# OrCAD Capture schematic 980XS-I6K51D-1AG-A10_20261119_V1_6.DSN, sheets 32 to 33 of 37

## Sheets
32 P0022_S2_USB/AUD/FLASH/XTAL: size A1
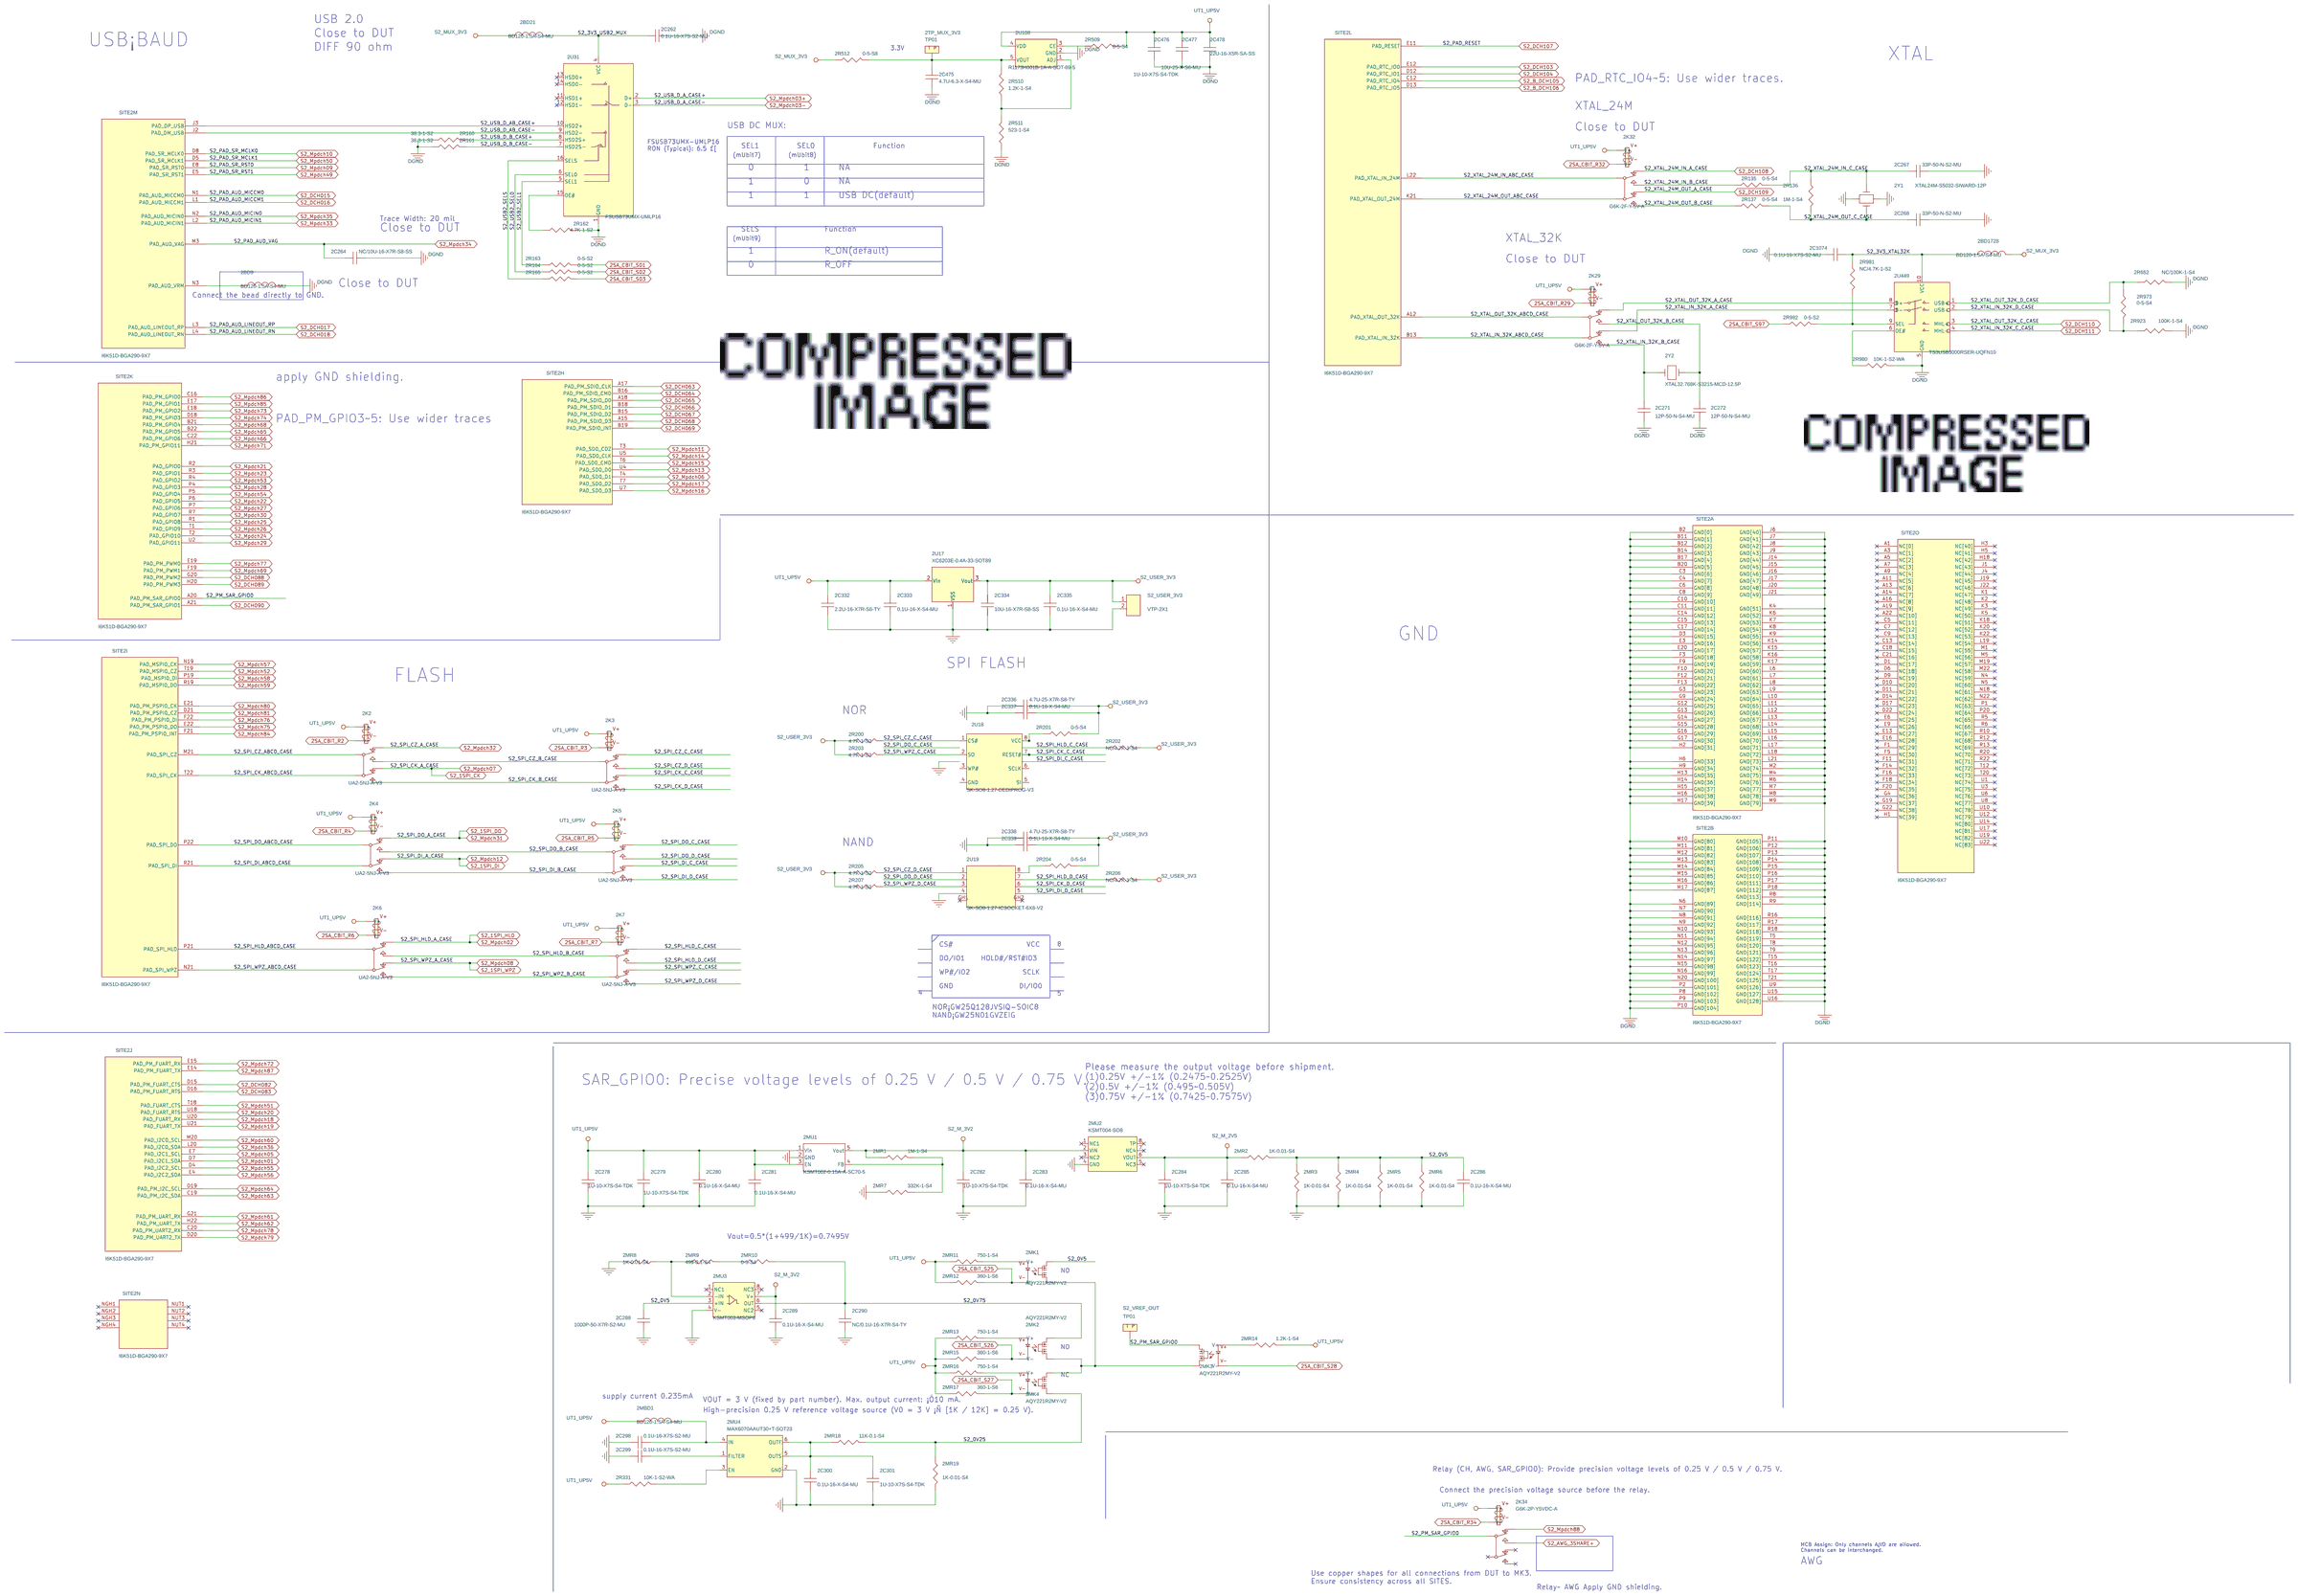
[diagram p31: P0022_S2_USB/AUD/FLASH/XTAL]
33 P0052_S5_USB/AUD/FLASH/XTAL: size A1
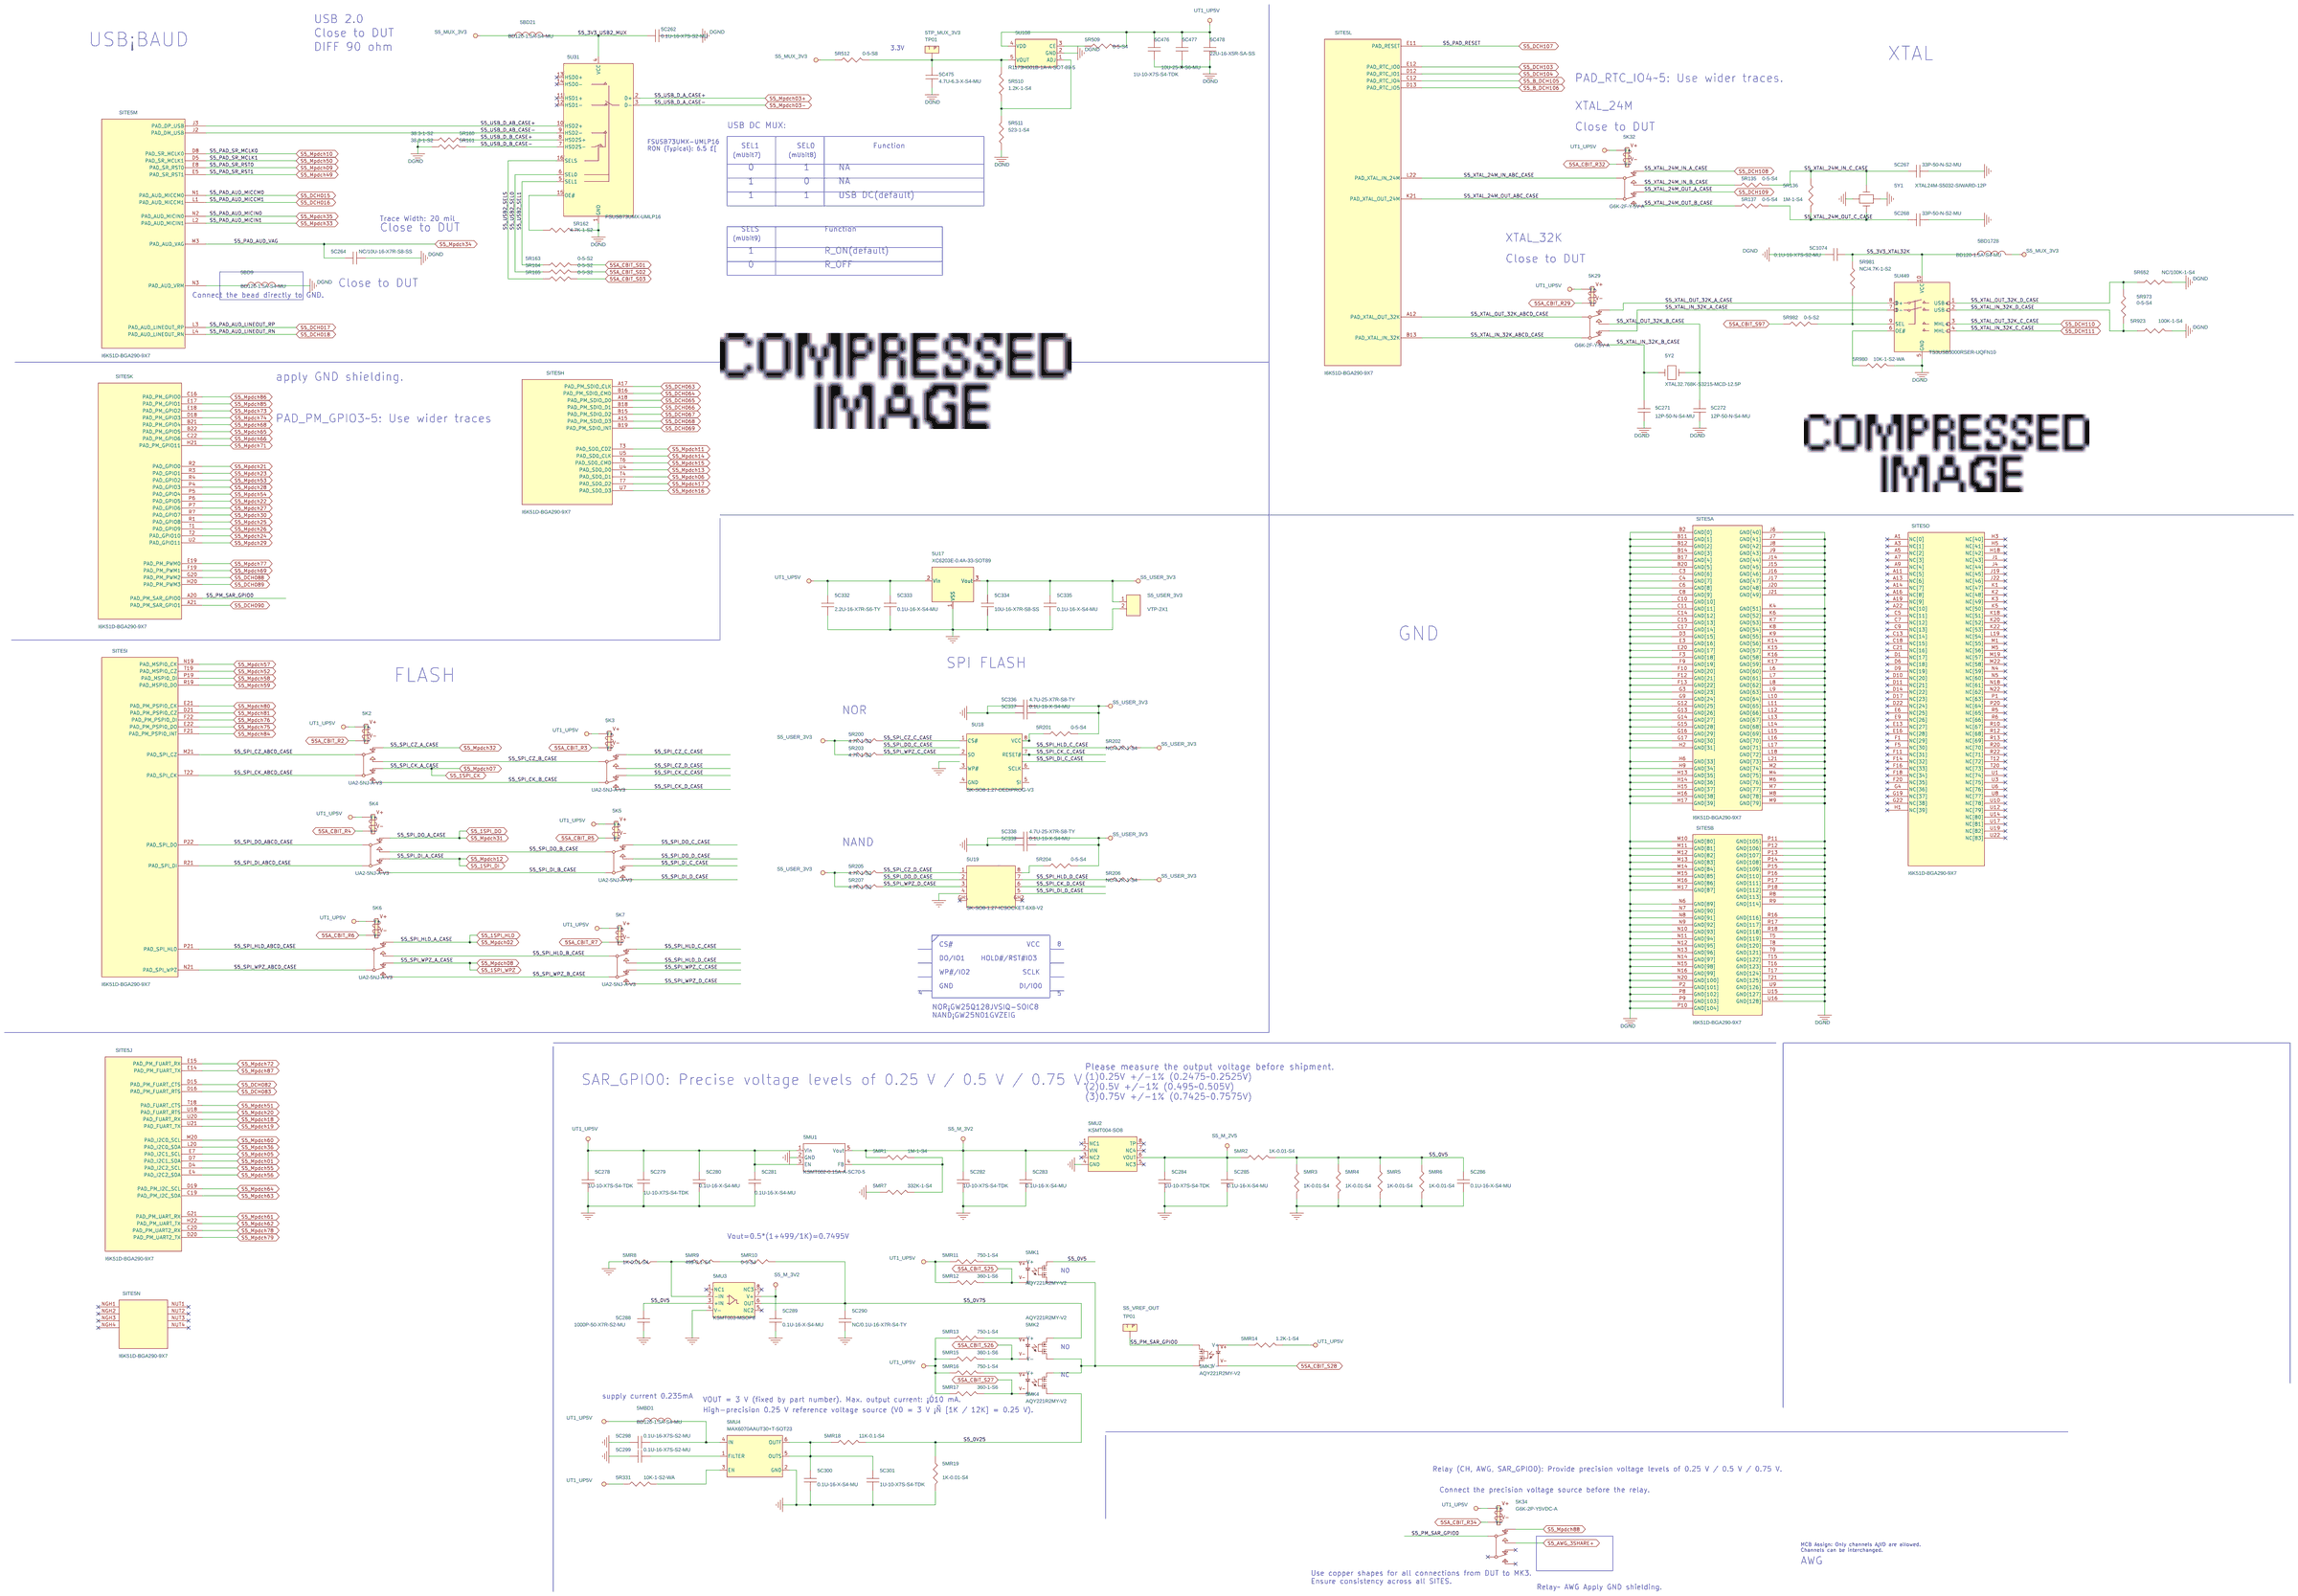
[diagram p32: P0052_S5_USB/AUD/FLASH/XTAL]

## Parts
sheet P0021_S2_POWER
SITE2  I6K51D-BGA290-9X7  [SK_TFBGA7X9_290P_0P4MM_JG]  (sections A,B,C,D,E,F,G,H,I,J,K,L,M,N,O)
sheet P0022_S2_USB/AUD/FLASH/XTAL
2BD9  BD120-1.5A-S4-MU  [FB0402]
2BD21  BD120-1.5A-S4-MU  [FB0402]
2BD1728  BD120-1.5A-S4-MU  [FB0402]
2C262  0.1U-16-X7S-S2-MU  [C0201]
2C264  NC/10U-16-X7R-S8-SS  [C0805]
2C267  33P-50-N-S2-MU  [C0201]
2C268  33P-50-N-S2-MU  [C0201]
2C271  12P-50-N-S4-MU  [C0402]
2C272  12P-50-N-S4-MU  [C0402]
2C278  1U-10-X7S-S4-TDK  [C0402]
2C279  1U-10-X7S-S4-TDK  [C0402]
2C280  0.1U-16-X-S4-MU  [C0402]
2C281  0.1U-16-X-S4-MU  [C0402]
2C282  1U-10-X7S-S4-TDK  [C0402]
2C283  0.1U-16-X-S4-MU  [C0402]
2C284  1U-10-X7S-S4-TDK  [C0402]
2C285  0.1U-16-X-S4-MU  [C0402]
2C286  0.1U-16-X-S4-MU  [C0402]
2C288  1000P-50-X7R-S2-MU  [C0201]
2C289  0.1U-16-X-S4-MU  [C0402]
2C290  NC/0.1U-16-X7R-S4-TY  [C0402]
2C298  0.1U-16-X7S-S2-MU  [C0201]
2C299  0.1U-16-X7S-S2-MU  [C0201]
2C300  0.1U-16-X-S4-MU  [C0402]
2C301  1U-10-X7S-S4-TDK  [C0402]
2C332  2.2U-16-X7R-S6-TY  [C0603]
2C333  0.1U-16-X-S4-MU  [C0402]
2C334  10U-16-X7R-S8-SS  [C0805]
2C335  0.1U-16-X-S4-MU  [C0402]
2C336  4.7U-25-X7R-S8-TY  [C0805]
2C337  0.1U-16-X-S4-MU  [C0402]
2C338  4.7U-25-X7R-S8-TY  [C0805]
2C339  0.1U-16-X-S4-MU  [C0402]
2C475  4.7U-6.3-X-S4-MU  [C0402]
2C476  1U-10-X7S-S4-TDK  [C0402]
2C477  10U-25-X-S6-MU  [C0603]
2C478  22U-16-X5R-SA-SS  [C1206]
2C1074  0.1U-16-X7S-S2-MU  [C0201_MINI]
2K2  UA2-5NJ-A-V3  [RL_NECUA2_5V_V3]
2K3  UA2-5NJ-A-V3  [RL_NECUA2_5V_V3]
2K4  UA2-5NJ-A-V3  [RL_NECUA2_5V_V3]
2K5  UA2-5NJ-A-V3  [RL_NECUA2_5V_V3]
2K6  UA2-5NJ-A-V3  [RL_NECUA2_5V_V3]
2K7  UA2-5NJ-A-V3  [RL_NECUA2_5V_V3]
2K29  G6K-2F-Y-5V-A  [RL_G6K2F-Y_5V_OMRON]
2K32  G6K-2F-Y-5V-A  [RL_G6K2F-Y_5V_OMRON]
2K34  G6K-2P-Y5VDC-A  [RL_OMRONG6K2PY_5V]
2MBD1  BD120-1.5A-S4-MU  [FB0402]
2MK1  AQY221R2MY-V2  [RL_AQY221R2MY_5V_V2]
2MK2  AQY221R2MY-V2  [RL_AQY221R2MY_5V_V2]
2MK3  AQY221R2MY-V2  [RL_AQY221R2MY_5V_V2]
2MK4  AQY221R2MY-V2  [RL_AQY221R2MY_5V_V2]
2MR1  1M-1-S4  [R0402_UNBGA_V2]
2MR2  1K-0.01-S4  [R0402_UNBGA_V2]
2MR3  1K-0.01-S4  [R0402_UNBGA_V2]
2MR4  1K-0.01-S4  [R0402_UNBGA_V2]
2MR5  1K-0.01-S4  [R0402_UNBGA_V2]
2MR6  1K-0.01-S4  [R0402_UNBGA_V2]
2MR7  332K-1-S4  [R0402_UNBGA_V2]
2MR8  1K-0.01-S4  [R0402_UNBGA_V2]
2MR9  499-0.1-S4  [R0402]
2MR10  0-5-S4  [R0402]
2MR11  750-1-S4  [R0402]
2MR12  360-1-S6  [R0603]
2MR13  750-1-S4  [R0402]
2MR14  1.2K-1-S4  [R0402]
2MR15  360-1-S6  [R0603]
2MR16  750-1-S4  [R0402]
2MR17  360-1-S6  [R0603]
2MR18  11K-0.1-S4  [R0402]
2MR19  1K-0.01-S4  [R0402_UNBGA_V2]
2MU1  KSMT002-0.15A-A-SC70-5  [SC70_5P]
2MU2  KSMT004-SO8  [SO8_244X127MM]
2MU3  KSMT003-MSOP8  [SO8_172X0P65MM]
2MU4  MAX6070AAUT30+T-SOT23  [SOT23_6P_0P95X2P7MM_H1P45MM]
2R135  0-5-S4  [R0402]
2R136  1M-1-S4  [R0402]
2R137  0-5-S4  [R0402]
2R160  38.3-1-S2  [R0201_MINI]
2R161  38.3-1-S2  [R0201_MINI]
2R162  4.7K-1-S2  [R0201_MINI]
2R163  0-5-S2  [R0201_MINI]
2R164  0-5-S2  [R0201_MINI]
2R165  0-5-S2  [R0201_MINI]
2R200  4.7K-1-S2  [R0201]
2R201  0-5-S4  [R0402]
2R202  NC/4.7K-1-S4  [R0402]
2R203  4.7K-1-S2  [R0201]
2R204  0-5-S4  [R0402]
2R205  4.7K-1-S2  [R0201]
2R206  NC/4.7K-1-S4  [R0402]
2R207  4.7K-1-S2  [R0201]
2R331  10K-1-S2-WA  [R0201]
2R509  0-5-S4  [R0402]
2R510  1.2K-1-S4  [R0402]
2R511  523-1-S4  [R0402]
2R512  0-5-S8  [R0805]
2R652  NC/100K-1-S4  [R0402]
2R923  100K-1-S4  [R0402]
2R973  0-5-S4  [R0402]
2R980  10K-1-S2-WA  [R0201]
2R981  NC/4.7K-1-S2  [R0201]
2R982  0-5-S2  [R0201]
2TP_MUX_3V3  TP01  [TP_040_T]
2U17  XC6203E-0.4A-33-SOT89  [SOT89]
2U18  SK-SO8-1.27-DEDIPROG-V3  [SK_SO8_1P27MM_DEDIPROG_V3]
2U19  SK-SO8-1.27-ICSOCKET-6X8-V2  [SK_SO8_1P27MM_SDQ54CBAA_V2]
2U31  FSUSB73UMX-UMLP16  [SW_UMLP2P6X1P8_12P_0P4MM]
2U108  R1173H001B-1A-A-SOT-89-5  [SOT_89_5]
2U449  TS3USB3000RSER-UQFN10  [UQFN2P05X1P55_10P_0P5MM]
2Y1  XTAL24M-S5032-SIWARD-12P  [XTAL_S_DUAL1]
2Y2  XTAL32.768K-S3215-MCD-12.5P  [XTAL_3P2X1P5MM_2P_MC]
S2_USER_3V3  VTP-2X1  [VTP_2P_100]
S2_VREF_OUT  TP01  [TP_040_T]
sheet P0052_S5_USB/AUD/FLASH/XTAL
5BD9  BD120-1.5A-S4-MU  [FB0402]
5BD21  BD120-1.5A-S4-MU  [FB0402]
5BD1728  BD120-1.5A-S4-MU  [FB0402]
5C262  0.1U-16-X7S-S2-MU  [C0201]
5C264  NC/10U-16-X7R-S8-SS  [C0805]
5C267  33P-50-N-S2-MU  [C0201]
5C268  33P-50-N-S2-MU  [C0201]
5C271  12P-50-N-S4-MU  [C0402]
5C272  12P-50-N-S4-MU  [C0402]
5C278  1U-10-X7S-S4-TDK  [C0402]
5C279  1U-10-X7S-S4-TDK  [C0402]
5C280  0.1U-16-X-S4-MU  [C0402]
5C281  0.1U-16-X-S4-MU  [C0402]
5C282  1U-10-X7S-S4-TDK  [C0402]
5C283  0.1U-16-X-S4-MU  [C0402]
5C284  1U-10-X7S-S4-TDK  [C0402]
5C285  0.1U-16-X-S4-MU  [C0402]
5C286  0.1U-16-X-S4-MU  [C0402]
5C288  1000P-50-X7R-S2-MU  [C0201]
5C289  0.1U-16-X-S4-MU  [C0402]
5C290  NC/0.1U-16-X7R-S4-TY  [C0402]
5C298  0.1U-16-X7S-S2-MU  [C0201]
5C299  0.1U-16-X7S-S2-MU  [C0201]
5C300  0.1U-16-X-S4-MU  [C0402]
5C301  1U-10-X7S-S4-TDK  [C0402]
5C332  2.2U-16-X7R-S6-TY  [C0603]
5C333  0.1U-16-X-S4-MU  [C0402]
5C334  10U-16-X7R-S8-SS  [C0805]
5C335  0.1U-16-X-S4-MU  [C0402]
5C336  4.7U-25-X7R-S8-TY  [C0805]
5C337  0.1U-16-X-S4-MU  [C0402]
5C338  4.7U-25-X7R-S8-TY  [C0805]
5C339  0.1U-16-X-S4-MU  [C0402]
5C475  4.7U-6.3-X-S4-MU  [C0402]
5C476  1U-10-X7S-S4-TDK  [C0402]
5C477  10U-25-X-S6-MU  [C0603]
5C478  22U-16-X5R-SA-SS  [C1206]
5C1074  0.1U-16-X7S-S2-MU  [C0201_MINI]
5K2  UA2-5NJ-A-V3  [RL_NECUA2_5V_V3]
5K3  UA2-5NJ-A-V3  [RL_NECUA2_5V_V3]
5K4  UA2-5NJ-A-V3  [RL_NECUA2_5V_V3]
5K5  UA2-5NJ-A-V3  [RL_NECUA2_5V_V3]
5K6  UA2-5NJ-A-V3  [RL_NECUA2_5V_V3]
5K7  UA2-5NJ-A-V3  [RL_NECUA2_5V_V3]
5K29  G6K-2F-Y-5V-A  [RL_G6K2F-Y_5V_OMRON]
5K32  G6K-2F-Y-5V-A  [RL_G6K2F-Y_5V_OMRON]
5K34  G6K-2P-Y5VDC-A  [RL_OMRONG6K2PY_5V]
5MBD1  BD120-1.5A-S4-MU  [FB0402]
5MK1  AQY221R2MY-V2  [RL_AQY221R2MY_5V_V2]
5MK2  AQY221R2MY-V2  [RL_AQY221R2MY_5V_V2]
5MK3  AQY221R2MY-V2  [RL_AQY221R2MY_5V_V2]
5MK4  AQY221R2MY-V2  [RL_AQY221R2MY_5V_V2]
5MR1  1M-1-S4  [R0402_UNBGA_V2]
5MR2  1K-0.01-S4  [R0402_UNBGA_V2]
5MR3  1K-0.01-S4  [R0402_UNBGA_V2]
5MR4  1K-0.01-S4  [R0402_UNBGA_V2]
5MR5  1K-0.01-S4  [R0402_UNBGA_V2]
5MR6  1K-0.01-S4  [R0402_UNBGA_V2]
5MR7  332K-1-S4  [R0402_UNBGA_V2]
5MR8  1K-0.01-S4  [R0402_UNBGA_V2]
5MR9  499-0.1-S4  [R0402]
5MR10  0-5-S4  [R0402]
5MR11  750-1-S4  [R0402]
5MR12  360-1-S6  [R0603]
5MR13  750-1-S4  [R0402]
5MR14  1.2K-1-S4  [R0402]
5MR15  360-1-S6  [R0603]
5MR16  750-1-S4  [R0402]
5MR17  360-1-S6  [R0603]
5MR18  11K-0.1-S4  [R0402]
5MR19  1K-0.01-S4  [R0402_UNBGA_V2]
5MU1  KSMT002-0.15A-A-SC70-5  [SC70_5P]
5MU2  KSMT004-SO8  [SO8_244X127MM]
5MU3  KSMT003-MSOP8  [SO8_172X0P65MM]
5MU4  MAX6070AAUT30+T-SOT23  [SOT23_6P_0P95X2P7MM_H1P45MM]
5R135  0-5-S4  [R0402]
5R136  1M-1-S4  [R0402]
5R137  0-5-S4  [R0402]
5R160  38.3-1-S2  [R0201_MINI]
5R161  38.3-1-S2  [R0201_MINI]
5R162  4.7K-1-S2  [R0201_MINI]
5R163  0-5-S2  [R0201_MINI]
5R164  0-5-S2  [R0201_MINI]
5R165  0-5-S2  [R0201_MINI]
5R200  4.7K-1-S2  [R0201]
5R201  0-5-S4  [R0402]
5R202  NC/4.7K-1-S4  [R0402]
5R203  4.7K-1-S2  [R0201]
5R204  0-5-S4  [R0402]
5R205  4.7K-1-S2  [R0201]
5R206  NC/4.7K-1-S4  [R0402]
5R207  4.7K-1-S2  [R0201]
5R331  10K-1-S2-WA  [R0201]
5R509  0-5-S4  [R0402]
5R510  1.2K-1-S4  [R0402]
5R511  523-1-S4  [R0402]
5R512  0-5-S8  [R0805]
5R652  NC/100K-1-S4  [R0402]
5R923  100K-1-S4  [R0402]
5R973  0-5-S4  [R0402]
5R980  10K-1-S2-WA  [R0201]
5R981  NC/4.7K-1-S2  [R0201]
5R982  0-5-S2  [R0201]
5TP_MUX_3V3  TP01  [TP_040_T]
5U17  XC6203E-0.4A-33-SOT89  [SOT89]
5U18  SK-SO8-1.27-DEDIPROG-V3  [SK_SO8_1P27MM_DEDIPROG_V3]
5U19  SK-SO8-1.27-ICSOCKET-6X8-V2  [SK_SO8_1P27MM_SDQ54CBAA_V2]
5U31  FSUSB73UMX-UMLP16  [SW_UMLP2P6X1P8_12P_0P4MM]
5U108  R1173H001B-1A-A-SOT-89-5  [SOT_89_5]
5U449  TS3USB3000RSER-UQFN10  [UQFN2P05X1P55_10P_0P5MM]
5Y1  XTAL24M-S5032-SIWARD-12P  [XTAL_S_DUAL1]
5Y2  XTAL32.768K-S3215-MCD-12.5P  [XTAL_3P2X1P5MM_2P_MC]
S5_USER_3V3  VTP-2X1  [VTP_2P_100]
S5_VREF_OUT  TP01  [TP_040_T]
SITE5  I6K51D-BGA290-9X7  [SK_TFBGA7X9_290P_0P4MM_JG]  (sections A,B,C,D,E,F,G,H,I,J,K,L,M,N,O)

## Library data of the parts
SITE2 SITE5 = I6K51D-BGA290-9X7
2BD9 5BD9 = BD120-1.5A-S4-MU: KAIROSNAME: BD9
2BD21 2BD1728 5BD21 5BD1728 = BD120-1.5A-S4-MU: KAIROSNAME: BD21
2C262 5C262 = 0.1U-16-X7S-S2-MU
2C264 5C264 = 10U-16-X7R-S8-SS: KAIROSNAME: C264
2C267 5C267 = 33P-50-N-S2-MU: KAIROSNAME: C267
2C268 5C268 = 33P-50-N-S2-MU: KAIROSNAME: C268
2C271 5C271 = 12P-50-N-S4-MU: KAIROSNAME: C271
2C272 5C272 = 12P-50-N-S4-MU: KAIROSNAME: C272
2C278 5C278 = 1U-10-X7S-S4-TDK: KAIROSNAME: C278
2C279 5C279 = 1U-10-X7S-S4-TDK: KAIROSNAME: C279
2C280 5C280 = 0.1U-16-X-S4-MU: KAIROSNAME: C280
2C281 5C281 = 0.1U-16-X-S4-MU: KAIROSNAME: C281
2C282 5C282 = 1U-10-X7S-S4-TDK: KAIROSNAME: C282
2C283 5C283 = 0.1U-16-X-S4-MU: KAIROSNAME: C283
2C284 5C284 = 1U-10-X7S-S4-TDK: KAIROSNAME: C284
2C285 5C285 = 0.1U-16-X-S4-MU: KAIROSNAME: C285
2C286 5C286 = 0.1U-16-X-S4-MU: KAIROSNAME: C286
2C288 5C288 = 1000P-50-X7R-S2-MU: KAIROSNAME: C288
2C289 5C289 = 0.1U-16-X-S4-MU: KAIROSNAME: C289
2C290 5C290 = 0.1U-16-X-S4-MU: KAIROSNAME: C290
2C298 5C298 = 0.1U-16-X7S-S2-MU: KAIROSNAME: C298
2C299 5C299 = 0.1U-16-X7S-S2-MU: KAIROSNAME: C299
2C300 5C300 = 0.1U-16-X-S4-MU: KAIROSNAME: C300
2C301 5C301 = 1U-10-X7S-S4-TDK: KAIROSNAME: C301
2C332 5C332 = 2.2U-16-X7R-S6-TY
2C333 2C335 2C337 2C339 5C333 5C335 5C337 5C339 = 0.1U-16-X-S4-MU
2C334 5C334 = 10U-16-X7R-S8-SS
2C336 2C338 5C336 5C338 = 4.7U-25-X7R-S8-TY
2C475 5C475 = 4.7U-6.3-X-S4-MU: KAIROSNAME: C475
2C476 5C476 = 1U-10-X-S4-MU: KAIROSNAME: C476
2C477 5C477 = 10U-25-X-S6-MU: KAIROSNAME: C477
2C478 5C478 = 22U-16-X5R-SA-SS: KAIROSNAME: C478
2C1074 5C1074 = 0.1U-16-X7S-S2-MU: KAIROSNAME: C262
2K2-2K7 5K2-5K7 = UA2-5NJ-A-V3
2K29 5K29 = G6K-2F-Y-5V-A: KAIROSNAME: K29
2K32 5K32 = G6K-2F-Y-5V-A: KAIROSNAME: K32
2K34 5K34 = G6K-2P-Y5VDC-A: KAIROSNAME: K34
2MBD1 5MBD1 = BD120-1.5A-S4-MU: KAIROSNAME: MBD1
2MK1 5MK1 = AQY221R2MY-V2: KAIROSNAME: MK1
2MK2 5MK2 = AQY221R2MY-V2: KAIROSNAME: MK2
2MK3 5MK3 = AQY221R2MY-V2: KAIROSNAME: MK3
2MK4 5MK4 = AQY221R2MY-V2: KAIROSNAME: MK4
2MR1 5MR1 = 1M-1-S4: KAIROSNAME: MR1
2MR2 5MR2 = 1K-0.01-S4: KAIROSNAME: MR2
2MR3 5MR3 = 1K-0.01-S4: KAIROSNAME: MR3
2MR4 5MR4 = 1K-0.01-S4: KAIROSNAME: MR4
2MR5 5MR5 = 1K-0.01-S4: KAIROSNAME: MR5
2MR6 5MR6 = 1K-0.01-S4: KAIROSNAME: MR6
2MR7 5MR7 = 332K-1-S4: KAIROSNAME: MR7
2MR8 5MR8 = 1K-0.01-S4: KAIROSNAME: MR8
2MR9 5MR9 = 499-0.1-S4: KAIROSNAME: MR9
2MR10 5MR10 = 0-5-S4: KAIROSNAME: MR10
2MR11 5MR11 = 750-1-S4: KAIROSNAME: MR11
2MR12 5MR12 = 360-1-S4: KAIROSNAME: MR12
2MR13 5MR13 = 750-1-S4: KAIROSNAME: MR13
2MR14 5MR14 = 1.2K-1-S4: KAIROSNAME: MR14
2MR15 5MR15 = 360-1-S4: KAIROSNAME: MR15
2MR16 5MR16 = 750-1-S4: KAIROSNAME: MR16
2MR17 5MR17 = 360-1-S4: KAIROSNAME: MR17
2MR18 5MR18 = 11K-0.1-S4: KAIROSNAME: MR18
2MR19 5MR19 = 1K-0.01-S4: KAIROSNAME: MR19
2MU1 5MU1 = KSMT002-0.15A-A-SC70-5: KAIROSNAME: MU1
2MU2 5MU2 = KSMT004-SO8: KAIROSNAME: MU2
2MU3 5MU3 = KSMT003-MSOP8: KAIROSNAME: MU3
2MU4 5MU4 = MAX6070AAUT30+T-SOT23: KAIROSNAME: MU4
2R135 5R135 = 0-5-S4: KAIROSNAME: R135
2R136 5R136 = 1M-1-S4: KAIROSNAME: R136
2R137 5R137 = 0-5-S4: KAIROSNAME: R137
2R160 5R160 = 38.3-1-S2: KAIROSNAME: R160
2R161 5R161 = 38.3-1-S2: KAIROSNAME: R161
2R162 5R162 = 4.7K-1-S2: KAIROSNAME: R162
2R163 5R163 = 0-5-S2: KAIROSNAME: R163
2R164 5R164 = 0-5-S2: KAIROSNAME: R164
2R165 5R165 = 0-5-S2: KAIROSNAME: R165
2R200 2R202 2R203 2R205-2R207 2R981 5R200 5R202 5R203 5R205-5R207 5R981 = 4.7K-1-S2
2R201 2R204 2R973 5R201 5R204 5R973 = 0-5-S4
2R331 5R331 = 10K-1-S2-WA: KAIROSNAME: R331
2R509 5R509 = 0-5-S4: KAIROSNAME: R509
2R510 5R510 = 1.2K-1-S4: KAIROSNAME: R510
2R511 5R511 = 523-1-S4: KAIROSNAME: R511
2R512 5R512 = 0-5-S8: KAIROSNAME: R512
2R652 2R923 5R652 5R923 = 100K-1-S4
2R980 5R980 = 10K-1-S2-WA
2R982 5R982 = 0-5-S2
2TP_MUX_3V3 5TP_MUX_3V3 = TP03-D: KAIROSNAME: TP_MUX_3V3
2U17 5U17 = XC6203E-0.4A-33-SOT89
2U18 5U18 = SK-SO8-1.27-DEDIPROG-V3
2U19 5U19 = SK-SO8-1.27-ICSOCKET-6X8-V2
2U31 5U31 = FSUSB73UMX-UMLP16: KAIROSNAME: U31
2U108 5U108 = R1173H001B-1A-A-SOT-89-5: KAIROSNAME: U108
2U449 5U449 = TS3USB3000RSER-UQFN10
2Y1 5Y1 = XTAL24M-S5032-SIWARD-12P: KAIROSNAME: Y1
2Y2 5Y2 = XTAL32.768K-S3215-MCD-12.5P: KAIROSNAME: Y2
S2_USER_3V3 S5_USER_3V3 = VTP-2X1
S2_VREF_OUT S5_VREF_OUT = TP01: KAIROSNAME: S1_VREF_OUT

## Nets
DGND: 2BD9.2 2C262.2 2C264.2 2C267.2 2C268.2 2C271.2 2C272.2 2C278.2 2C279.2 2C280.2 2C281.2 2C282.2 2C283.2 2C284.2 2C285.2 2C286.2 2C288.2 2C289.2 2C290.2 2C298.1 2C299.1 2C300.2 2C301.2 2C332.2 2C333.2 2C334.2 2C335.2 2C336.1 2C337.1 2C338.1 2C339.1 2C475.2 2C476.2 2C477.2 2C478.2 2C1074.2 2MR3.2 2MR4.2 2MR5.2 2MR6.2 2MR7.1 2MR8.2 2MR19.2 2MU1.2(GND) 2MU2.4(GND) 2MU3.4(V-) 2MU4.2(GND) 2R160.1 2R161.1 2R162.2 2R511.2 2R652.2 2R923.2 2R980.2 2U17.1(VSS) 2U19.4 2U31.1(GND) 2U108.2(GND) 2U449.5(GND) 2Y1.2 2Y1.4 5BD9.2 5C262.2 5C264.2 5C267.2 5C268.2 5C271.2 5C272.2 5C278.2 5C279.2 5C280.2 5C281.2 5C282.2 5C283.2 5C284.2 5C285.2 5C286.2 5C288.2 5C289.2 5C290.2 5C298.1 5C299.1 5C300.2 5C301.2 5C332.2 5C333.2 5C334.2 5C335.2 5C336.1 5C337.1 5C338.1 5C339.1 5C475.2 5C476.2 5C477.2 5C478.2 5C1074.2 5MR3.2 5MR4.2 5MR5.2 5MR6.2 5MR7.1 5MR8.2 5MR19.2 5MU1.2(GND) 5MU2.4(GND) 5MU3.4(V-) 5MU4.2(GND) 5R160.1 5R161.1 5R162.2 5R511.2 5R652.2 5R923.2 5R980.2 5U17.1(VSS) 5U19.4 5U31.1(GND) 5U108.2(GND) 5U449.5(GND) 5Y1.2 5Y1.4 S2_USER_3V3.2 S5_USER_3V3.2 SITE2.B2(GND[0]) SITE2.B11(GND[1]) SITE2.B12(GND[2]) SITE2.B14(GND[3]) SITE2.B17(GND[4]) SITE2.B20(GND[5]) SITE2.C3(GND[6]) SITE2.C4(GND[7]) SITE2.C6(GND[8]) SITE2.C8(GND[9]) SITE2.C10(GND[10]) SITE2.C11(GND[11]) SITE2.C14(GND[12]) SITE2.C15(GND[13]) SITE2.C17(GND[14]) SITE2.D3(GND[15]) SITE2.E3(GND[16]) SITE2.E20(GND[17]) SITE2.F3(GND[18]) SITE2.F9(GND[19]) SITE2.F10(GND[20]) SITE2.F12(GND[21]) SITE2.F13(GND[22]) SITE2.G3(GND[23]) SITE2.G9(GND[24]) SITE2.G12(GND[25]) SITE2.G13(GND[26]) SITE2.G14(GND[27]) SITE2.G15(GND[28]) SITE2.G16(GND[29]) SITE2.G17(GND[30]) SITE2.H2(GND[31]) SITE2.H6(GND[33]) SITE2.H9(GND[34]) SITE2.H13(GND[35]) SITE2.H14(GND[36]) SITE2.H15(GND[37]) SITE2.H16(GND[38]) SITE2.H17(GND[39]) SITE2.J6(GND[40]) SITE2.J7(GND[41]) SITE2.J8(GND[42]) SITE2.J9(GND[43]) SITE2.J14(GND[44]) SITE2.J15(GND[45]) SITE2.J16(GND[46]) SITE2.J17(GND[47]) SITE2.J20(GND[48]) SITE2.J21(GND[49]) SITE2.K4(GND[51]) SITE2.K6(GND[52]) SITE2.K7(GND[53]) SITE2.K8(GND[54]) SITE2.K9(GND[55]) SITE2.K14(GND[56]) SITE2.K15(GND[57]) SITE2.K16(GND[58]) SITE2.K17(GND[59]) SITE2.L6(GND[60]) SITE2.L7(GND[61]) SITE2.L8(GND[62]) SITE2.L9(GND[63]) SITE2.L10(GND[64]) SITE2.L11(GND[65]) SITE2.L12(GND[66]) SITE2.L13(GND[67]) SITE2.L14(GND[68]) SITE2.L15(GND[69]) SITE2.L16(GND[70]) SITE2.L17(GND[71]) SITE2.L18(GND[72]) SITE2.L21(GND[73]) SITE2.M2(GND[74]) SITE2.M4(GND[75]) SITE2.M6(GND[76]) SITE2.M7(GND[77]) SITE2.M8(GND[78]) SITE2.M9(GND[79]) SITE2.M10(GND[80]) SITE2.M11(GND[81]) SITE2.M12(GND[82]) SITE2.M13(GND[83]) SITE2.M14(GND[84]) SITE2.M15(GND[85]) SITE2.M16(GND[86]) SITE2.M17(GND[87]) SITE2.N6(GND[89]) SITE2.N7(GND[90]) SITE2.N8(GND[91]) SITE2.N9(GND[92]) SITE2.N10(GND[93]) SITE2.N11(GND[94]) SITE2.N12(GND[95]) SITE2.N13(GND[96]) SITE2.N14(GND[97]) SITE2.N15(GND[98]) SITE2.N16(GND[99]) SITE2.N20(GND[100]) SITE2.P2(GND[101]) SITE2.P8(GND[102]) SITE2.P9(GND[103]) SITE2.P10(GND[104]) SITE2.P11(GND[105]) SITE2.P12(GND[106]) SITE2.P13(GND[107]) SITE2.P14(GND[108]) SITE2.P15(GND[109]) SITE2.P16(GND[110]) SITE2.P17(GND[111]) SITE2.P18(GND[112]) SITE2.R8(GND[113]) SITE2.R9(GND[114]) SITE2.R16(GND[116]) SITE2.R17(GND[117]) SITE2.R18(GND[118]) SITE2.T5(GND[119]) SITE2.T8(GND[120]) SITE2.T9(GND[121]) SITE2.T15(GND[122]) SITE2.T16(GND[123]) SITE2.T17(GND[124]) SITE2.T21(GND[125]) SITE2.U9(GND[126]) SITE2.U15(GND[127]) SITE2.U16(GND[128]) SITE5.B2(GND[0]) SITE5.B11(GND[1]) SITE5.B12(GND[2]) SITE5.B14(GND[3]) SITE5.B17(GND[4]) SITE5.B20(GND[5]) SITE5.C3(GND[6]) SITE5.C4(GND[7]) SITE5.C6(GND[8]) SITE5.C8(GND[9]) SITE5.C10(GND[10]) SITE5.C11(GND[11]) SITE5.C14(GND[12]) SITE5.C15(GND[13]) SITE5.C17(GND[14]) SITE5.D3(GND[15]) SITE5.E3(GND[16]) SITE5.E20(GND[17]) SITE5.F3(GND[18]) SITE5.F9(GND[19]) SITE5.F10(GND[20]) SITE5.F12(GND[21]) SITE5.F13(GND[22]) SITE5.G3(GND[23]) SITE5.G9(GND[24]) SITE5.G12(GND[25]) SITE5.G13(GND[26]) SITE5.G14(GND[27]) SITE5.G15(GND[28]) SITE5.G16(GND[29]) SITE5.G17(GND[30]) SITE5.H2(GND[31]) SITE5.H6(GND[33]) SITE5.H9(GND[34]) SITE5.H13(GND[35]) SITE5.H14(GND[36]) SITE5.H15(GND[37]) SITE5.H16(GND[38]) SITE5.H17(GND[39]) SITE5.J6(GND[40]) SITE5.J7(GND[41]) SITE5.J8(GND[42]) SITE5.J9(GND[43]) SITE5.J14(GND[44]) SITE5.J15(GND[45]) SITE5.J16(GND[46]) SITE5.J17(GND[47]) SITE5.J20(GND[48]) SITE5.J21(GND[49]) SITE5.K4(GND[51]) SITE5.K6(GND[52]) SITE5.K7(GND[53]) SITE5.K8(GND[54]) SITE5.K9(GND[55]) SITE5.K14(GND[56]) SITE5.K15(GND[57]) SITE5.K16(GND[58]) SITE5.K17(GND[59]) SITE5.L6(GND[60]) SITE5.L7(GND[61]) SITE5.L8(GND[62]) SITE5.L9(GND[63]) SITE5.L10(GND[64]) SITE5.L11(GND[65]) SITE5.L12(GND[66]) SITE5.L13(GND[67]) SITE5.L14(GND[68]) SITE5.L15(GND[69]) SITE5.L16(GND[70]) SITE5.L17(GND[71]) SITE5.L18(GND[72]) SITE5.L21(GND[73]) SITE5.M2(GND[74]) SITE5.M4(GND[75]) SITE5.M6(GND[76]) SITE5.M7(GND[77]) SITE5.M8(GND[78]) SITE5.M9(GND[79]) SITE5.M10(GND[80]) SITE5.M11(GND[81]) SITE5.M12(GND[82]) SITE5.M13(GND[83]) SITE5.M14(GND[84]) SITE5.M15(GND[85]) SITE5.M16(GND[86]) SITE5.M17(GND[87]) SITE5.N6(GND[89]) SITE5.N7(GND[90]) SITE5.N8(GND[91]) SITE5.N9(GND[92]) SITE5.N10(GND[93]) SITE5.N11(GND[94]) SITE5.N12(GND[95]) SITE5.N13(GND[96]) SITE5.N14(GND[97]) SITE5.N15(GND[98]) SITE5.N16(GND[99]) SITE5.N20(GND[100]) SITE5.P2(GND[101]) SITE5.P8(GND[102]) SITE5.P9(GND[103]) SITE5.P10(GND[104]) SITE5.P11(GND[105]) SITE5.P12(GND[106]) SITE5.P13(GND[107]) SITE5.P14(GND[108]) SITE5.P15(GND[109]) SITE5.P16(GND[110]) SITE5.P17(GND[111]) SITE5.P18(GND[112]) SITE5.R8(GND[113]) SITE5.R9(GND[114]) SITE5.R16(GND[116]) SITE5.R17(GND[117]) SITE5.R18(GND[118]) SITE5.T5(GND[119]) SITE5.T8(GND[120]) SITE5.T9(GND[121]) SITE5.T15(GND[122]) SITE5.T16(GND[123]) SITE5.T17(GND[124]) SITE5.T21(GND[125]) SITE5.U9(GND[126]) SITE5.U15(GND[127]) SITE5.U16(GND[128]) ; also on sheet 1 2 3 4 5 6 7 8 9 10 11 12 13 14 17 18 19 20 21 22 23 24 25 26 27 28 30 31 34 35 36 37
2SA_CBIT_R2: 2K2.8(V-)
2SA_CBIT_R3: 2K3.8(V-)
2SA_CBIT_R4: 2K4.8(V-)
2SA_CBIT_R5: 2K5.8(V-)
2SA_CBIT_R6: 2K6.8(V-)
2SA_CBIT_R7: 2K7.8(V-)
2SA_CBIT_R29: 2K29.8(V-)
2SA_CBIT_R32: 2K32.8(V-)
2SA_CBIT_R34: 2K34.8(V-)
2SA_CBIT_S01: 2R163.1
2SA_CBIT_S02: 2R164.1
2SA_CBIT_S03: 2R165.1
2SA_CBIT_S25: 2MK1.2(V-) 2MR12.2
2SA_CBIT_S26: 2MK2.2(V-) 2MR15.2
2SA_CBIT_S27: 2MK4.2(V-) 2MR17.2
2SA_CBIT_S28: 2MK3.2(V-)
2SA_CBIT_S97: 2R982.1
5SA_CBIT_R2: 5K2.8(V-)
5SA_CBIT_R3: 5K3.8(V-)
5SA_CBIT_R4: 5K4.8(V-)
5SA_CBIT_R5: 5K5.8(V-)
5SA_CBIT_R6: 5K6.8(V-)
5SA_CBIT_R7: 5K7.8(V-)
5SA_CBIT_R29: 5K29.8(V-)
5SA_CBIT_R32: 5K32.8(V-)
5SA_CBIT_R34: 5K34.8(V-)
5SA_CBIT_S01: 5R163.1
5SA_CBIT_S02: 5R164.1
5SA_CBIT_S03: 5R165.1
5SA_CBIT_S25: 5MK1.2(V-) 5MR12.2
5SA_CBIT_S26: 5MK2.2(V-) 5MR15.2
5SA_CBIT_S27: 5MK4.2(V-) 5MR17.2
5SA_CBIT_S28: 5MK3.2(V-)
5SA_CBIT_S97: 5R982.1
S2_0V5: 2C286.1 2C288.1 2MK1.4 2MR2.2 2MR3.1 2MR4.1 2MR5.1 2MR6.1 2MU3.3(+IN)
S2_0V25: 2MK4.3 2MR18.2 2MR19.1
S2_0V75: 2C290.1 2MK2.4 2MR10.2 2MU3.6(OUT)
S2_1SPI_CK: 2K2.7
S2_1SPI_DI: 2K4.7
S2_1SPI_DO: 2K4.2
S2_1SPI_HLD: 2K6.2
S2_1SPI_WPZ: 2K6.7
S2_3V3_USB2_MUX: 2BD21.2 2C262.1 2U31.4(VCC)
S2_3V3_XTAL32K: 2BD1728.2 2C1074.1 2R981.1 2U449.10(VCC)
S2_AWG_3SHARE+: 2K34.4 ; also on sheet 20
S2_B_DCH105: SITE2.C12(PAD_RTC_IO4)
S2_B_DCH106: SITE2.D13(PAD_RTC_IO5)
S2_DCH015: SITE2.N1(PAD_AUD_MICCM0)
S2_DCH016: SITE2.L1(PAD_AUD_MICCM1)
S2_DCH017: SITE2.L3(PAD_AUD_LINEOUT_RP)
S2_DCH018: SITE2.L4(PAD_AUD_LINEOUT_RN)
S2_DCH063: SITE2.A17(PAD_PM_SDIO_CLK)
S2_DCH064: SITE2.B16(PAD_PM_SDIO_CMD)
S2_DCH065: SITE2.A18(PAD_PM_SDIO_D0)
S2_DCH066: SITE2.B18(PAD_PM_SDIO_D1)
S2_DCH067: SITE2.B15(PAD_PM_SDIO_D2)
S2_DCH068: SITE2.A15(PAD_PM_SDIO_D3)
S2_DCH069: SITE2.B19(PAD_PM_SDIO_INT)
S2_DCH082: SITE2.D15(PAD_PM_FUART_CTS)
S2_DCH083: SITE2.D16(PAD_PM_FUART_RTS)
S2_DCH088: SITE2.G20(PAD_PM_PWM2)
S2_DCH089: SITE2.H20(PAD_PM_PWM3)
S2_DCH090: SITE2.A21(PAD_PM_SAR_GPIO1)
S2_DCH103: SITE2.E12(PAD_RTC_IO0)
S2_DCH104: SITE2.D12(PAD_RTC_IO1)
S2_DCH107: SITE2.E11(PAD_RESET)
S2_DCH108: 2K32.2
S2_DCH109: 2K32.7
S2_DCH110: 2U449.3(MHL+)
S2_DCH111: 2U449.4(MHL-)
S2_M_2V5: 2C284.1 2C285.1 2MR2.1 2MU2.6(VOUT)
S2_M_3V2: 2C282.1 2C283.1 2C289.1 2MR1.1 2MU1.5(Vout) 2MU2.2(VIN) 2MU3.7(V+)
S2_Mpdch01: SITE2.D7(PAD_I2C1_SDA)
S2_Mpdch03+: 2U31.2(D+)
S2_Mpdch03-: 2U31.3(D-)
S2_Mpdch05: SITE2.E7(PAD_I2C1_SCL)
S2_Mpdch06: SITE2.T4(PAD_SD0_D1)
S2_Mpdch09: SITE2.E8(PAD_SR_RST0)
S2_Mpdch10: SITE2.D8(PAD_SR_MCLK0)
S2_Mpdch11: SITE2.T3(PAD_SD0_CDZ)
S2_Mpdch13: SITE2.U4(PAD_SD0_D0)
S2_Mpdch14: SITE2.U5(PAD_SD0_CLK)
S2_Mpdch15: SITE2.T6(PAD_SD0_CMD)
S2_Mpdch16: SITE2.U7(PAD_SD0_D3)
S2_Mpdch17: SITE2.T7(PAD_SD0_D2)
S2_Mpdch18: SITE2.U20(PAD_FUART_RX)
S2_Mpdch19: SITE2.U21(PAD_FUART_TX)
S2_Mpdch20: SITE2.U18(PAD_FUART_RTS)
S2_Mpdch21: SITE2.R2(PAD_GPIO0)
S2_Mpdch22: SITE2.P6(PAD_GPIO5)
S2_Mpdch23: SITE2.R3(PAD_GPIO1)
S2_Mpdch24: SITE2.T2(PAD_GPIO10)
S2_Mpdch25: SITE2.R1(PAD_GPIO8)
S2_Mpdch26: SITE2.T1(PAD_GPIO9)
S2_Mpdch27: SITE2.P7(PAD_GPIO6)
S2_Mpdch28: SITE2.P4(PAD_GPIO3)
S2_Mpdch29: SITE2.U2(PAD_GPIO11)
S2_Mpdch30: SITE2.R7(PAD_GPIO7)
S2_Mpdch32: 2K2.2
S2_Mpdch33: SITE2.L2(PAD_AUD_MICIN1)
S2_Mpdch34: 2C264.1 SITE2.M3(PAD_AUD_VAG)
S2_Mpdch35: SITE2.N2(PAD_AUD_MICIN0)
S2_Mpdch36: SITE2.L20(PAD_I2C0_SDA)
S2_Mpdch49: SITE2.E5(PAD_SR_RST1)
S2_Mpdch50: SITE2.D5(PAD_SR_MCLK1)
S2_Mpdch51: SITE2.T18(PAD_FUART_CTS)
S2_Mpdch52: SITE2.T19(PAD_MSPI0_CZ)
S2_Mpdch53: SITE2.R4(PAD_GPIO2)
S2_Mpdch54: SITE2.P5(PAD_GPIO4)
S2_Mpdch55: SITE2.D4(PAD_I2C2_SCL)
S2_Mpdch56: SITE2.E4(PAD_I2C2_SDA)
S2_Mpdch57: SITE2.N19(PAD_MSPI0_CK)
S2_Mpdch58: SITE2.P19(PAD_MSPI0_DI)
S2_Mpdch59: SITE2.R19(PAD_MSPI0_DO)
S2_Mpdch60: SITE2.M20(PAD_I2C0_SCL)
S2_Mpdch61: SITE2.G21(PAD_PM_UART_RX)
S2_Mpdch62: SITE2.H22(PAD_PM_UART_TX)
S2_Mpdch63: SITE2.C19(PAD_PM_I2C_SDA)
S2_Mpdch64: SITE2.D19(PAD_PM_I2C_SCL)
S2_Mpdch65: SITE2.B22(PAD_PM_GPIO5)
S2_Mpdch66: SITE2.C22(PAD_PM_GPIO6)
S2_Mpdch68: SITE2.B21(PAD_PM_GPIO4)
S2_Mpdch69: SITE2.F19(PAD_PM_PWM1)
S2_Mpdch71: SITE2.H21(PAD_PM_GPIO11)
S2_Mpdch72: SITE2.E15(PAD_PM_FUART_RX)
S2_Mpdch73: SITE2.E18(PAD_PM_GPIO2)
S2_Mpdch74: SITE2.D18(PAD_PM_GPIO3)
S2_Mpdch75: SITE2.E22(PAD_PM_PSPI0_DO)
S2_Mpdch76: SITE2.F22(PAD_PM_PSPI0_DI)
S2_Mpdch77: SITE2.E19(PAD_PM_PWM0)
S2_Mpdch78: SITE2.C20(PAD_PM_UART2_RX)
S2_Mpdch79: SITE2.D20(PAD_PM_UART2_TX)
S2_Mpdch80: SITE2.E21(PAD_PM_PSPI0_CK)
S2_Mpdch81: SITE2.D21(PAD_PM_PSPI0_CZ)
S2_Mpdch84: SITE2.F21(PAD_PM_PSPI0_INT)
S2_Mpdch85: SITE2.E17(PAD_PM_GPIO1)
S2_Mpdch86: SITE2.C16(PAD_PM_GPIO0)
S2_Mpdch87: SITE2.E14(PAD_PM_FUART_TX)
S2_Mpdch88: 2K34.2
S2_MUX_3V3: 2BD21.1 2BD1728.1 2R512.1 ; also on sheet 13
S2_PM_SAR_GPIO0: 2K34.3 2MK3.4 S2_VREF_OUT.1(TP) SITE2.A20(PAD_PM_SAR_GPIO0)
S2_SPI_CK_ABCD_CASE: 2K2.6 SITE2.T22(PAD_SPI_CK)
S2_SPI_CK_B_CASE: 2K2.5 2K3.6
S2_SPI_CK_C_CASE: 2K3.7 2U18.7(RESET#)
S2_SPI_CK_D_CASE: 2K3.5 2U19.6
S2_SPI_CZ_ABCD_CASE: 2K2.3 SITE2.M21(PAD_SPI_CZ)
S2_SPI_CZ_B_CASE: 2K2.4 2K3.3
S2_SPI_CZ_C_CASE: 2K3.2 2R200.2 2U18.1(CS#)
S2_SPI_CZ_D_CASE: 2K3.4 2R205.2 2U19.1
S2_SPI_DI_ABCD_CASE: 2K4.6 SITE2.R21(PAD_SPI_DI)
S2_SPI_DI_B_CASE: 2K4.5 2K5.6
S2_SPI_DI_C_CASE: 2K5.7
S2_SPI_DI_D_CASE: 2K5.5 2U19.5
S2_SPI_DO_ABCD_CASE: 2K4.3 SITE2.P22(PAD_SPI_DO)
S2_SPI_DO_B_CASE: 2K4.4 2K5.3
S2_SPI_DO_C_CASE: 2K5.2
S2_SPI_DO_D_CASE: 2K5.4 2U19.2
S2_SPI_HLD_ABCD_CASE: 2K6.3 SITE2.P21(PAD_SPI_HLD)
S2_SPI_HLD_B_CASE: 2K6.4 2K7.3
S2_SPI_HLD_C_CASE: 2K7.2 2R202.1
S2_SPI_HLD_D_CASE: 2K7.4 2R206.1 2U19.7
S2_SPI_WPZ_ABCD_CASE: 2K6.6 SITE2.N21(PAD_SPI_WPZ)
S2_SPI_WPZ_B_CASE: 2K6.5 2K7.6
S2_SPI_WPZ_C_CASE: 2K7.7 2R203.2 2U18.2(SO)
S2_SPI_WPZ_D_CASE: 2K7.5 2R207.2 2U19.3
S2_USB2_SEL0: 2R164.2 2U31.6(SEL0)
S2_USB2_SEL1: 2R163.2 2U31.5(SEL1)
S2_USB2_SELS: 2R165.2 2U31.16(SELS)
S2_USB_D_AB_CASE+: 2U31.10(HSD2+) SITE2.J3(PAD_DP_USB)
S2_USB_D_AB_CASE-: 2U31.9(HSD2-) SITE2.J2(PAD_DM_USB)
S2_USB_D_B_CASE+: 2R160.2 2U31.8(HSD2S+)
S2_USB_D_B_CASE-: 2R161.2 2U31.7(HSD2S-)
S2_USER_3V3: 2C334.1 2C335.1 2C336.2 2C337.2 2C338.2 2C339.2 2R200.1 2R201.2 2R202.2 2R203.1 2R204.2 2R205.1 2R206.2 2R207.1 2U17.3(Vout) S2_USER_3V3.1
S2_XTAL_24M_IN_ABC_CASE: 2K32.3 SITE2.L22(PAD_XTAL_IN_24M)
S2_XTAL_24M_IN_B_CASE: 2K32.4 2R135.1
S2_XTAL_24M_IN_C_CASE: 2C267.1 2R135.2 2R136.2 2Y1.3
S2_XTAL_24M_OUT_ABC_CASE: 2K32.6 SITE2.K21(PAD_XTAL_OUT_24M)
S2_XTAL_24M_OUT_B_CASE: 2K32.5 2R137.1
S2_XTAL_24M_OUT_C_CASE: 2C268.1 2R136.1 2R137.2 2Y1.1
S2_XTAL_IN_32K_A_CASE: 2K29.7 2U449.7(D-)
S2_XTAL_IN_32K_ABCD_CASE: 2K29.6 SITE2.B13(PAD_XTAL_IN_32K)
S2_XTAL_IN_32K_B_CASE: 2C271.1 2K29.5 2Y2.1
S2_XTAL_IN_32K_D_CASE: 2R923.1 2R973.2 2U449.2(USB-)
S2_XTAL_OUT_32K_A_CASE: 2K29.2 2U449.8(D+)
S2_XTAL_OUT_32K_ABCD_CASE: 2K29.3 SITE2.A12(PAD_XTAL_OUT_32K)
S2_XTAL_OUT_32K_B_CASE: 2C272.1 2K29.4 2Y2.2
S2_XTAL_OUT_32K_D_CASE: 2R652.1 2R973.1 2U449.1(USB+)
S5_0V5: 5C286.1 5C288.1 5MK1.4 5MR2.2 5MR3.1 5MR4.1 5MR5.1 5MR6.1 5MU3.3(+IN)
S5_0V25: 5MK4.3 5MR18.2 5MR19.1
S5_0V75: 5C290.1 5MK2.4 5MR10.2 5MU3.6(OUT)
S5_1SPI_CK: 5K2.7
S5_1SPI_DI: 5K4.7
S5_1SPI_DO: 5K4.2
S5_1SPI_HLD: 5K6.2
S5_1SPI_WPZ: 5K6.7
S5_3V3_USB2_MUX: 5BD21.2 5C262.1 5U31.4(VCC)
S5_3V3_XTAL32K: 5BD1728.2 5C1074.1 5R981.1 5U449.10(VCC)
S5_AWG_3SHARE+: 5K34.4 ; also on sheet 20
S5_B_DCH105: SITE5.C12(PAD_RTC_IO4)
S5_B_DCH106: SITE5.D13(PAD_RTC_IO5)
S5_DCH015: SITE5.N1(PAD_AUD_MICCM0)
S5_DCH016: SITE5.L1(PAD_AUD_MICCM1)
S5_DCH017: SITE5.L3(PAD_AUD_LINEOUT_RP)
S5_DCH018: SITE5.L4(PAD_AUD_LINEOUT_RN)
S5_DCH063: SITE5.A17(PAD_PM_SDIO_CLK)
S5_DCH064: SITE5.B16(PAD_PM_SDIO_CMD)
S5_DCH065: SITE5.A18(PAD_PM_SDIO_D0)
S5_DCH066: SITE5.B18(PAD_PM_SDIO_D1)
S5_DCH067: SITE5.B15(PAD_PM_SDIO_D2)
S5_DCH068: SITE5.A15(PAD_PM_SDIO_D3)
S5_DCH069: SITE5.B19(PAD_PM_SDIO_INT)
S5_DCH082: SITE5.D15(PAD_PM_FUART_CTS)
S5_DCH083: SITE5.D16(PAD_PM_FUART_RTS)
S5_DCH088: SITE5.G20(PAD_PM_PWM2)
S5_DCH089: SITE5.H20(PAD_PM_PWM3)
S5_DCH090: SITE5.A21(PAD_PM_SAR_GPIO1)
S5_DCH103: SITE5.E12(PAD_RTC_IO0)
S5_DCH104: SITE5.D12(PAD_RTC_IO1)
S5_DCH107: SITE5.E11(PAD_RESET)
S5_DCH108: 5K32.2
S5_DCH109: 5K32.7
S5_DCH110: 5U449.3(MHL+)
S5_DCH111: 5U449.4(MHL-)
S5_M_2V5: 5C284.1 5C285.1 5MR2.1 5MU2.6(VOUT)
S5_M_3V2: 5C282.1 5C283.1 5C289.1 5MR1.1 5MU1.5(Vout) 5MU2.2(VIN) 5MU3.7(V+)
S5_Mpdch01: SITE5.D7(PAD_I2C1_SDA)
S5_Mpdch03+: 5U31.2(D+)
S5_Mpdch03-: 5U31.3(D-)
S5_Mpdch05: SITE5.E7(PAD_I2C1_SCL)
S5_Mpdch06: SITE5.T4(PAD_SD0_D1)
S5_Mpdch09: SITE5.E8(PAD_SR_RST0)
S5_Mpdch10: SITE5.D8(PAD_SR_MCLK0)
S5_Mpdch11: SITE5.T3(PAD_SD0_CDZ)
S5_Mpdch13: SITE5.U4(PAD_SD0_D0)
S5_Mpdch14: SITE5.U5(PAD_SD0_CLK)
S5_Mpdch15: SITE5.T6(PAD_SD0_CMD)
S5_Mpdch16: SITE5.U7(PAD_SD0_D3)
S5_Mpdch17: SITE5.T7(PAD_SD0_D2)
S5_Mpdch18: SITE5.U20(PAD_FUART_RX)
S5_Mpdch19: SITE5.U21(PAD_FUART_TX)
S5_Mpdch20: SITE5.U18(PAD_FUART_RTS)
S5_Mpdch21: SITE5.R2(PAD_GPIO0)
S5_Mpdch22: SITE5.P6(PAD_GPIO5)
S5_Mpdch23: SITE5.R3(PAD_GPIO1)
S5_Mpdch24: SITE5.T2(PAD_GPIO10)
S5_Mpdch25: SITE5.R1(PAD_GPIO8)
S5_Mpdch26: SITE5.T1(PAD_GPIO9)
S5_Mpdch27: SITE5.P7(PAD_GPIO6)
S5_Mpdch28: SITE5.P4(PAD_GPIO3)
S5_Mpdch29: SITE5.U2(PAD_GPIO11)
S5_Mpdch30: SITE5.R7(PAD_GPIO7)
S5_Mpdch32: 5K2.2
S5_Mpdch33: SITE5.L2(PAD_AUD_MICIN1)
S5_Mpdch34: 5C264.1 SITE5.M3(PAD_AUD_VAG)
S5_Mpdch35: SITE5.N2(PAD_AUD_MICIN0)
S5_Mpdch36: SITE5.L20(PAD_I2C0_SDA)
S5_Mpdch49: SITE5.E5(PAD_SR_RST1)
S5_Mpdch50: SITE5.D5(PAD_SR_MCLK1)
S5_Mpdch51: SITE5.T18(PAD_FUART_CTS)
S5_Mpdch52: SITE5.T19(PAD_MSPI0_CZ)
S5_Mpdch53: SITE5.R4(PAD_GPIO2)
S5_Mpdch54: SITE5.P5(PAD_GPIO4)
S5_Mpdch55: SITE5.D4(PAD_I2C2_SCL)
S5_Mpdch56: SITE5.E4(PAD_I2C2_SDA)
S5_Mpdch57: SITE5.N19(PAD_MSPI0_CK)
S5_Mpdch58: SITE5.P19(PAD_MSPI0_DI)
S5_Mpdch59: SITE5.R19(PAD_MSPI0_DO)
S5_Mpdch60: SITE5.M20(PAD_I2C0_SCL)
S5_Mpdch61: SITE5.G21(PAD_PM_UART_RX)
S5_Mpdch62: SITE5.H22(PAD_PM_UART_TX)
S5_Mpdch63: SITE5.C19(PAD_PM_I2C_SDA)
S5_Mpdch64: SITE5.D19(PAD_PM_I2C_SCL)
S5_Mpdch65: SITE5.B22(PAD_PM_GPIO5)
S5_Mpdch66: SITE5.C22(PAD_PM_GPIO6)
S5_Mpdch68: SITE5.B21(PAD_PM_GPIO4)
S5_Mpdch69: SITE5.F19(PAD_PM_PWM1)
S5_Mpdch71: SITE5.H21(PAD_PM_GPIO11)
S5_Mpdch72: SITE5.E15(PAD_PM_FUART_RX)
S5_Mpdch73: SITE5.E18(PAD_PM_GPIO2)
S5_Mpdch74: SITE5.D18(PAD_PM_GPIO3)
S5_Mpdch75: SITE5.E22(PAD_PM_PSPI0_DO)
S5_Mpdch76: SITE5.F22(PAD_PM_PSPI0_DI)
S5_Mpdch77: SITE5.E19(PAD_PM_PWM0)
S5_Mpdch78: SITE5.C20(PAD_PM_UART2_RX)
S5_Mpdch79: SITE5.D20(PAD_PM_UART2_TX)
S5_Mpdch80: SITE5.E21(PAD_PM_PSPI0_CK)
S5_Mpdch81: SITE5.D21(PAD_PM_PSPI0_CZ)
S5_Mpdch84: SITE5.F21(PAD_PM_PSPI0_INT)
S5_Mpdch85: SITE5.E17(PAD_PM_GPIO1)
S5_Mpdch86: SITE5.C16(PAD_PM_GPIO0)
S5_Mpdch87: SITE5.E14(PAD_PM_FUART_TX)
S5_Mpdch88: 5K34.2
S5_MUX_3V3: 5BD21.1 5BD1728.1 5R512.1 ; also on sheet 7
S5_PM_SAR_GPIO0: 5K34.3 5MK3.4 S5_VREF_OUT.1(TP) SITE5.A20(PAD_PM_SAR_GPIO0)
S5_SPI_CK_ABCD_CASE: 5K2.6 SITE5.T22(PAD_SPI_CK)
S5_SPI_CK_B_CASE: 5K2.5 5K3.6
S5_SPI_CK_C_CASE: 5K3.7 5U18.7(RESET#)
S5_SPI_CK_D_CASE: 5K3.5 5U19.6
S5_SPI_CZ_ABCD_CASE: 5K2.3 SITE5.M21(PAD_SPI_CZ)
S5_SPI_CZ_B_CASE: 5K2.4 5K3.3
S5_SPI_CZ_C_CASE: 5K3.2 5R200.2 5U18.1(CS#)
S5_SPI_CZ_D_CASE: 5K3.4 5R205.2 5U19.1
S5_SPI_DI_ABCD_CASE: 5K4.6 SITE5.R21(PAD_SPI_DI)
S5_SPI_DI_B_CASE: 5K4.5 5K5.6
S5_SPI_DI_C_CASE: 5K5.7
S5_SPI_DI_D_CASE: 5K5.5 5U19.5
S5_SPI_DO_ABCD_CASE: 5K4.3 SITE5.P22(PAD_SPI_DO)
S5_SPI_DO_B_CASE: 5K4.4 5K5.3
S5_SPI_DO_C_CASE: 5K5.2
S5_SPI_DO_D_CASE: 5K5.4 5U19.2
S5_SPI_HLD_ABCD_CASE: 5K6.3 SITE5.P21(PAD_SPI_HLD)
S5_SPI_HLD_B_CASE: 5K6.4 5K7.3
S5_SPI_HLD_C_CASE: 5K7.2 5R202.1
S5_SPI_HLD_D_CASE: 5K7.4 5R206.1 5U19.7
S5_SPI_WPZ_ABCD_CASE: 5K6.6 SITE5.N21(PAD_SPI_WPZ)
S5_SPI_WPZ_B_CASE: 5K6.5 5K7.6
S5_SPI_WPZ_C_CASE: 5K7.7 5R203.2 5U18.2(SO)
S5_SPI_WPZ_D_CASE: 5K7.5 5R207.2 5U19.3
S5_USB2_SEL0: 5R164.2 5U31.6(SEL0)
S5_USB2_SEL1: 5R163.2 5U31.5(SEL1)
S5_USB2_SELS: 5R165.2 5U31.16(SELS)
S5_USB_D_AB_CASE+: 5U31.10(HSD2+) SITE5.J3(PAD_DP_USB)
S5_USB_D_AB_CASE-: 5U31.9(HSD2-) SITE5.J2(PAD_DM_USB)
S5_USB_D_B_CASE+: 5R160.2 5U31.8(HSD2S+)
S5_USB_D_B_CASE-: 5R161.2 5U31.7(HSD2S-)
S5_USER_3V3: 5C334.1 5C335.1 5C336.2 5C337.2 5C338.2 5C339.2 5R200.1 5R201.2 5R202.2 5R203.1 5R204.2 5R205.1 5R206.2 5R207.1 5U17.3(Vout) S5_USER_3V3.1
S5_XTAL_24M_IN_ABC_CASE: 5K32.3 SITE5.L22(PAD_XTAL_IN_24M)
S5_XTAL_24M_IN_B_CASE: 5K32.4 5R135.1
S5_XTAL_24M_IN_C_CASE: 5C267.1 5R135.2 5R136.2 5Y1.3
S5_XTAL_24M_OUT_ABC_CASE: 5K32.6 SITE5.K21(PAD_XTAL_OUT_24M)
S5_XTAL_24M_OUT_B_CASE: 5K32.5 5R137.1
S5_XTAL_24M_OUT_C_CASE: 5C268.1 5R136.1 5R137.2 5Y1.1
S5_XTAL_IN_32K_A_CASE: 5K29.7 5U449.7(D-)
S5_XTAL_IN_32K_ABCD_CASE: 5K29.6 SITE5.B13(PAD_XTAL_IN_32K)
S5_XTAL_IN_32K_B_CASE: 5C271.1 5K29.5 5Y2.1
S5_XTAL_IN_32K_D_CASE: 5R923.1 5R973.2 5U449.2(USB-)
S5_XTAL_OUT_32K_A_CASE: 5K29.2 5U449.8(D+)
S5_XTAL_OUT_32K_ABCD_CASE: 5K29.3 SITE5.A12(PAD_XTAL_OUT_32K)
S5_XTAL_OUT_32K_B_CASE: 5C272.1 5K29.4 5Y2.2
S5_XTAL_OUT_32K_D_CASE: 5R652.1 5R973.1 5U449.1(USB+)
UT1_UP5V: 2C278.1 2C279.1 2C280.1 2C281.1 2C332.1 2C333.1 2C476.1 2C477.1 2C478.1 2K2.1(V+) 2K3.1(V+) 2K4.1(V+) 2K5.1(V+) 2K6.1(V+) 2K7.1(V+) 2K29.1(V+) 2K32.1(V+) 2K34.1(V+) 2MBD1.1 2MR11.1 2MR12.1 2MR13.1 2MR14.2 2MR15.1 2MR16.1 2MR17.1 2MU1.1(Vin) 2MU1.3(EN) 2R331.1 2R509.2 2U17.2(Vin) 2U108.4(VDD) 5C278.1 5C279.1 5C280.1 5C281.1 5C332.1 5C333.1 5C476.1 5C477.1 5C478.1 5K2.1(V+) 5K3.1(V+) 5K4.1(V+) 5K5.1(V+) 5K6.1(V+) 5K7.1(V+) 5K29.1(V+) 5K32.1(V+) 5K34.1(V+) 5MBD1.1 5MR11.1 5MR12.1 5MR13.1 5MR14.2 5MR15.1 5MR16.1 5MR17.1 5MU1.1(Vin) 5MU1.3(EN) 5R331.1 5R509.2 5U17.2(Vin) 5U108.4(VDD) ; also on sheet 2 4 6 8 10 12 14 17 19 20 21 22 23 24 25 26 27 28 30 31 34 35 36 37
N22558345: 2R162.1 2U31.15(OE#)
N22558370: 2R510.2 2R511.1 2U108.1(ADJ)
N22558376: 2C475.1 2R510.1 2R512.2 2TP_MUX_3V3.1(TP) 2U108.5(VOUT)
N22558377: 2R509.1 2U108.3(CE)
N22558731: 2BD9.1 SITE2.N3(PAD_AUD_VRM)
N22558735: 2MU4.3(EN) 2R331.2
N22558769: 2C299.2 2MU4.1(FILTER)
N22558770: 2C300.1 2C301.1 2MR18.1 2MU4.5(OUTS) 2MU4.6(OUTF)
N22558775: 2C298.2 2MBD1.2 2MU4.4(IN)
N22558804: 2MR1.2 2MR7.2 2MU1.4(FB)
N22558814: 2MR8.1 2MR9.1 2MU3.2(-IN)
N22558851: 2MK2.1(V+) 2MR13.2
N22558856: 2MK1.3 2MK2.3 2MK3.3 2MK4.4
N22558863: 2MK3.1(V+) 2MR14.1
N22558867: 2MK4.1(V+) 2MR16.2
N22558888: 2MR9.2 2MR10.1
N22558889: 2MK1.1(V+) 2MR11.2
N22559057: 2R980.1 2U449.6(OE#)
N22559068: 2R981.2 2R982.2 2U449.9(SEL)
N22559190: 2R204.1 2U19.8
N22559210: 2R201.1 2U18.8(VCC)
N22581990: 5R162.1 5U31.15(OE#)
N22582015: 5R510.2 5R511.1 5U108.1(ADJ)
N22582021: 5C475.1 5R510.1 5R512.2 5TP_MUX_3V3.1(TP) 5U108.5(VOUT)
N22582022: 5R509.1 5U108.3(CE)
N22582318: 5BD9.1 SITE5.N3(PAD_AUD_VRM)
N22582322: 5MU4.3(EN) 5R331.2
N22582356: 5C299.2 5MU4.1(FILTER)
N22582357: 5C300.1 5C301.1 5MR18.1 5MU4.5(OUTS) 5MU4.6(OUTF)
N22582362: 5C298.2 5MBD1.2 5MU4.4(IN)
N22582391: 5MR1.2 5MR7.2 5MU1.4(FB)
N22582401: 5MR8.1 5MR9.1 5MU3.2(-IN)
N22582438: 5MK2.1(V+) 5MR13.2
N22582443: 5MK1.3 5MK2.3 5MK3.3 5MK4.4
N22582450: 5MK3.1(V+) 5MR14.1
N22582454: 5MK4.1(V+) 5MR16.2
N22582475: 5MR9.2 5MR10.1
N22582476: 5MK1.1(V+) 5MR11.2
N22582644: 5R980.1 5U449.6(OE#)
N22582655: 5R981.2 5R982.2 5U449.9(SEL)
N22582777: 5R204.1 5U19.8
N22582797: 5R201.1 5U18.8(VCC)

Not connected (* = marked no-connect by the designer): 2K34 5* 6* 7*; 2MU2 1(NC1)* 3(NC2)* 5(NC3)* 7(NC4)* 8(TP)*; 2MU3 1(NC1)* 5(NC2)* 8(NC3)*; 2U18 3(WP#) 4(GND) 5(SI) 6(SCLK); 2U19 GH1* GH2*; 2U31 11(HSD1+)* 12(HSD1-)* 13(HSD0+)* 14(HSD0-)*; 5K34 5* 6* 7*; 5MU2 1(NC1)* 3(NC2)* 5(NC3)* 7(NC4)* 8(TP)*; 5MU3 1(NC1)* 5(NC2)* 8(NC3)*; 5U18 3(WP#) 4(GND) 5(SI) 6(SCLK); 5U19 GH1* GH2*; 5U31 11(HSD1+)* 12(HSD1-)* 13(HSD0+)* 14(HSD0-)*; SITE2 A1(NC[0])* A3(NC[1])* A5(NC[2])* A7(NC[3])* A9(NC[4])* A11(NC[5])* A13(NC[6])* A14(NC[7])* A16(NC[8])* A19(NC[9])* A22(NC[10])* C5(NC[11])* C7(NC[12])* C9(NC[13])* C13(NC[14])* C18(NC[15])* C21(NC[16])* D1(NC[17])* D6(NC[18])* D9(NC[19])* D10(NC[20])* D11(NC[21])* D14(NC[22])* D17(NC[23])* D22(NC[24])* E6(NC[25])* E9(NC[26])* E13(NC[27])* E16(NC[28])* F1(NC[29])* F5(NC[30])* F11(NC[31])* F14(NC[32])* F16(NC[33])* F18(NC[34])* F20(NC[35])* G4(NC[36])* G19(NC[37])* G22(NC[38])* H1(NC[39])* H3(NC[40])* H5(NC[41])* H18(NC[42])* J1(NC[43])* J4(NC[44])* J19(NC[45])* J22(NC[46])* K1(NC[47])* K2(NC[48])* K3(NC[49])* K5(NC[50])* K18(NC[51])* K20(NC[52])* K22(NC[53])* L19(NC[54])* M1(NC[55])* M5(NC[56])* M19(NC[57])* M22(NC[58])* N4(NC[59])* N5(NC[60])* N18(NC[61])* N22(NC[62])* NGH1* NGH2* NGH3* NGH4* NUT1* NUT2* NUT3* NUT4* P1(NC[63])* P20(NC[64])* R5(NC[65])* R6(NC[66])* R10(NC[67])* R12(NC[68])* R13(NC[69])* R20(NC[70])* R22(NC[71])* T12(NC[72])* T20(NC[73])* U1(NC[74])* U3(NC[75])* U6(NC[76])* U8(NC[77])* U10(NC[78])* U12(NC[79])* U14(NC[80])* U17(NC[81])* U19(NC[82])* U22(NC[83])*; SITE5 A1(NC[0])* A3(NC[1])* A5(NC[2])* A7(NC[3])* A9(NC[4])* A11(NC[5])* A13(NC[6])* A14(NC[7])* A16(NC[8])* A19(NC[9])* A22(NC[10])* C5(NC[11])* C7(NC[12])* C9(NC[13])* C13(NC[14])* C18(NC[15])* C21(NC[16])* D1(NC[17])* D6(NC[18])* D9(NC[19])* D10(NC[20])* D11(NC[21])* D14(NC[22])* D17(NC[23])* D22(NC[24])* E6(NC[25])* E9(NC[26])* E13(NC[27])* E16(NC[28])* F1(NC[29])* F5(NC[30])* F11(NC[31])* F14(NC[32])* F16(NC[33])* F18(NC[34])* F20(NC[35])* G4(NC[36])* G19(NC[37])* G22(NC[38])* H1(NC[39])* H3(NC[40])* H5(NC[41])* H18(NC[42])* J1(NC[43])* J4(NC[44])* J19(NC[45])* J22(NC[46])* K1(NC[47])* K2(NC[48])* K3(NC[49])* K5(NC[50])* K18(NC[51])* K20(NC[52])* K22(NC[53])* L19(NC[54])* M1(NC[55])* M5(NC[56])* M19(NC[57])* M22(NC[58])* N4(NC[59])* N5(NC[60])* N18(NC[61])* N22(NC[62])* NGH1* NGH2* NGH3* NGH4* NUT1* NUT2* NUT3* NUT4* P1(NC[63])* P20(NC[64])* R5(NC[65])* R6(NC[66])* R10(NC[67])* R12(NC[68])* R13(NC[69])* R20(NC[70])* R22(NC[71])* T12(NC[72])* T20(NC[73])* U1(NC[74])* U3(NC[75])* U6(NC[76])* U8(NC[77])* U10(NC[78])* U12(NC[79])* U14(NC[80])* U17(NC[81])* U19(NC[82])* U22(NC[83])*

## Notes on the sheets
sheet 32
- USB 2.0
- Close to DUT
- USB¡BAUD
- DIFF 90 ohm
- 3.3V
- XTAL
- PAD_RTC_IO4~5: Use wider traces.
- XTAL_24M
- USB DC MUX:
- Close to DUT
- FSUSB73UMX-UMLP16
  RON (Typical): 6.5 £[
- SEL1
- SEL0
- Function
- (mUbit7)
- (mUbit8)
- 0
- 1
- NA
- 1
- 0
- NA
- 1
- 1
- USB DC(default)
- Trace Width: 20 mil
- Close to DUT
- SELS
- Function
- XTAL_32K
- (mUbit9)
- 1
- R_ON(default)
- Close to DUT
- 0
- R_OFF
- Close to DUT
- Connect the bead directly to GND.
- apply GND shielding.
- PAD_PM_GPIO3~5: Use wider traces
- GND
- SPI FLASH
- FLASH
- NOR
- NAND
- CS#
- VCC
- 8
- DO/IO1
- HOLD#/RST#IO3
- WP#/IO2
- SCLK
- GND
- DI/IO0
- 4
- 5
- NOR¡GW25Q128JVSIQ-SOIC8
  NAND¡GW25N01GVZEIG
- Please measure the output voltage before shipment.
  (1)0.25V +/-1% (0.2475~0.2525V)
  (2)0.5V +/-1% (0.495~0.505V)
  (3)0.75V +/-1% (0.7425~0.7575V)
- SAR_GPIO0: Precise voltage levels of 0.25 V / 0.5 V / 0.75 V.
- Vout=0.5*(1+499/1K)=0.7495V
- NO
- NO
- NC
- supply current 0.235mA
- VOUT = 3 V (fixed by part number). Max. output current: ¡Ó10 mA.
- High-precision 0.25 V reference voltage source (V0 = 3 V ¡Ñ [1K / 12K] = 0.25 V).
- Relay (CH, AWG, SAR_GPIO0): Provide precision voltage levels of 0.25 V / 0.5 V / 0.75 V.
- Connect the precision voltage source before the relay.
- MCB Assign: Only channels A¡VD are allowed.
  Channels can be interchanged.
- AWG
- Use copper shapes for all connections from DUT to MK3.
  Ensure consistency across all SITES.
- Relay~ AWG Apply GND shielding.
sheet 33
- USB 2.0
- Close to DUT
- USB¡BAUD
- DIFF 90 ohm
- 3.3V
- XTAL
- PAD_RTC_IO4~5: Use wider traces.
- XTAL_24M
- USB DC MUX:
- Close to DUT
- FSUSB73UMX-UMLP16
  RON (Typical): 6.5 £[
- SEL1
- SEL0
- Function
- (mUbit7)
- (mUbit8)
- 0
- 1
- NA
- 1
- 0
- NA
- 1
- 1
- USB DC(default)
- Trace Width: 20 mil
- Close to DUT
- SELS
- Function
- XTAL_32K
- (mUbit9)
- 1
- R_ON(default)
- Close to DUT
- 0
- R_OFF
- Close to DUT
- Connect the bead directly to GND.
- apply GND shielding.
- PAD_PM_GPIO3~5: Use wider traces
- GND
- SPI FLASH
- FLASH
- NOR
- NAND
- CS#
- VCC
- 8
- DO/IO1
- HOLD#/RST#IO3
- WP#/IO2
- SCLK
- GND
- DI/IO0
- 4
- 5
- NOR¡GW25Q128JVSIQ-SOIC8
  NAND¡GW25N01GVZEIG
- Please measure the output voltage before shipment.
  (1)0.25V +/-1% (0.2475~0.2525V)
  (2)0.5V +/-1% (0.495~0.505V)
  (3)0.75V +/-1% (0.7425~0.7575V)
- SAR_GPIO0: Precise voltage levels of 0.25 V / 0.5 V / 0.75 V.
- Vout=0.5*(1+499/1K)=0.7495V
- NO
- NO
- NC
- supply current 0.235mA
- VOUT = 3 V (fixed by part number). Max. output current: ¡Ó10 mA.
- High-precision 0.25 V reference voltage source (V0 = 3 V ¡Ñ [1K / 12K] = 0.25 V).
- Relay (CH, AWG, SAR_GPIO0): Provide precision voltage levels of 0.25 V / 0.5 V / 0.75 V.
- Connect the precision voltage source before the relay.
- MCB Assign: Only channels A¡VD are allowed.
  Channels can be interchanged.
- AWG
- Use copper shapes for all connections from DUT to MK3.
  Ensure consistency across all SITES.
- Relay~ AWG Apply GND shielding.
